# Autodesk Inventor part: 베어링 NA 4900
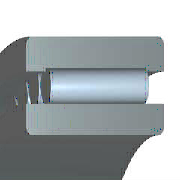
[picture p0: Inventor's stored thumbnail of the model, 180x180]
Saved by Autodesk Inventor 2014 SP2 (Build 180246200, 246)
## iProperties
Created: 2009-02
Part Number: 베어링 NA 4900
Material: 스테인리스강
Description: 니들 롤러 베어링 - 경계 치수 및 공차
Document SubType Name: Modeling
Standard: KS B 2029
Designer: SeoGD™
Standards Organization: KS
Language: ko-KR
Size Designation: NA 4900 - 10 x 22 x 13
Categories: <MemberInstance><Categories><Category DisplayName="샤프트 부품" InternalName="7f7aeb1f-a693-4053-b835-cee3144e0d98" Mnemonic="SHFT"><Category DisplayName="베어링" Inter
Density: 8.08 g/cm^3
Appearance: 반광택
Mass: 24.488 g
Surface Area: 38.613 cm^2
Volume: 3.0307 cm^3
IsCustomPart: 0
Author: SeoGD™
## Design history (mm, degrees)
sketch "스케치"
  geometry: L1 (1.857, 9)-(11.143, 9); L2 (11.143, 9)-(11.143, 7); L3 (13, 7)-(0, 7); L4 (1.857, 7)-(1.857, 9); L5 (1.857, 8)-(11.143, 8); L6 (6.5, 8)-(6.5, 7); L7 (0, 5)-(13, 5); L8 (0, 11)-(13, 11); L9 (13, 5)-(13, 7); L10 (13, 8.8)-(13, 11); L11 (1.857, 8.8)-(0, 8.8); L12 (11.143, 8.8)-(13, 8.8); L13 (-6, 0)-(36, 0) reference; L14 (0, -1.9)-(0, 14.9) reference
  constraints: 24 end point, 8 point on line, 3 midpoint, 3 parallel, 3 perpendicular, 2 symmetric about line, 1 horizontal, 1 other
  dimensions: "d6" = 10 diameter of L7 L13 (= WD); "d7" = 14 diameter of L3 L13 (= KID1); "d8" = 22 diameter of L8 L13 (= BD); "d9" = 16 diameter of L6.start L13 (= 0.5 x WD + 0.5 x BD); "d10" = 17.6 diameter of L12 L13 (= 0.9 x BD + 0.9 x WD - 0.8 x KID1); "d11" = 18 diameter of L1 L13 (= BD + WD - KID1); "d12" = 1.85714 distance between parallel lines of L14 L4 (= 0.142857 x KB); "d13" = 13 distance between parallel lines of L14 L9 (= KB); "d14" = 11.14286 distance between parallel lines of L14 L2 (= 0.857143 x KB)
revolve "본체" stored, may be unused: angle "d17" = 90 deg
revolve "롤러" stored, may be unused: angle "d18" = 90 deg
pattern_circular "IDS_ARRAYROLLER[SIMPL:T]" dims angle "d2" = 360 deg
body "Solid1"
fillet "모깎기1" dims "d0" = 0.3 (= KRS)
other parameters: "WD" = 10 [user parameter; used in 6 equation terms], "BD" = 22 [user parameter; used in 6 equation terms], "KB" = 13 [user parameter; used in 3 equation terms], "KID1" = 14 [user parameter; used in 4 equation terms], "KRS" = 0.3 [user parameter; used in 1 equation term], "d3" = 0, "d4" = 0, "d5" = 0, "d15" = 0, "d16" = 0, "BC0" = 9150000 [user parameter], "WR" = 5 (= 0.5 x WD) [user parameter], "BBA" = 0 [user parameter], "BC" = 8150000 [user parameter], "BR" = 11 (= 0.5 x BD) [user parameter]
